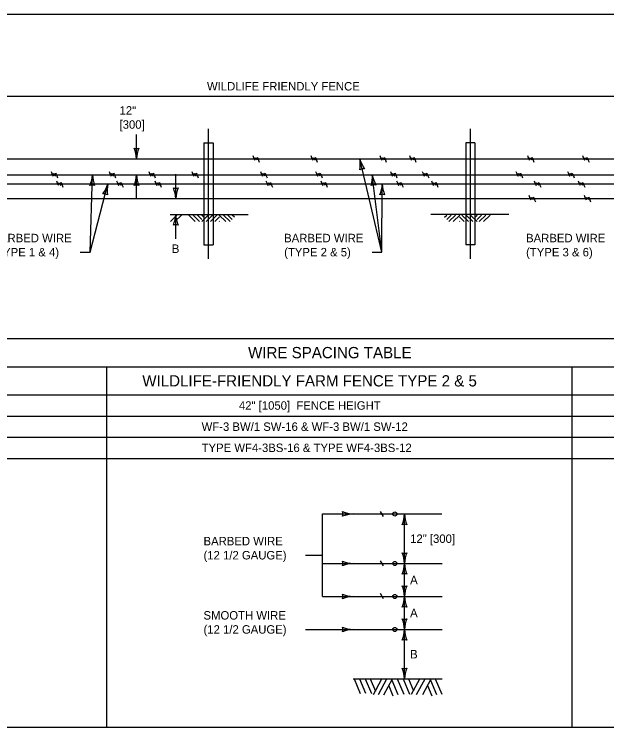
# Model space of a CAD drawing. Extents: x 49991.4 to 50021, y 49987.6 to 50011.4.
# Drawn here: x 50013.03 to 50017.23, y 50003.02 to 50008.16 of the extents above; entities that cross this region are included whole.
import ezdxf

# ---------------------------------------------------------------- set-up
doc = ezdxf.new("R2010")
doc.units = 0
for name, color, linetype in [('Level 1', 7, 'Continuous'), ('Level 2', 7, 'Continuous'), ('Level 3', 7, 'Continuous'), ('Level 4', 7, 'Continuous'), ('Level 5', 7, 'Continuous')]:
    doc.layers.add(name, color=color, linetype=linetype)

msp = doc.modelspace()

# ---------------------------------------------------------------- linework, layer by layer
at = {"layer": 'Level 1'}
for p, q in [((50014.3766, 50007.2536), (50014.3766, 50006.7473)), ((50014.3766, 50007.2536), (50014.4423, 50007.2536)), ((50014.4423, 50007.2536), (50014.4423, 50006.7473)), ((50016.2329, 50007.2536), (50016.2329, 50006.7473)), ((50016.2986, 50007.2536), (50016.2329, 50007.2536)), ((50016.2986, 50007.2536), (50016.2986, 50006.7473)), ((50012.5204, 50007.1411), (50018.1548, 50007.1411)), ((50012.5204, 50007.0286), (50018.1548, 50007.0286)), ((50012.5204, 50006.963), (50018.1548, 50006.963)), ((50010.2459, 50006.8598), (50020.4293, 50006.8598)), ((50014.1372, 50006.7473), (50014.6898, 50006.7473)), ((50014.1398, 50006.6964), (50014.186, 50006.7427)), ((50014.1706, 50006.6964), (50014.2169, 50006.7427)), ((50014.3153, 50006.6964), (50014.2691, 50006.7427)), ((50014.3462, 50006.6964), (50014.2999, 50006.7427)), ((50014.3616, 50006.7118), (50014.3307, 50006.7427)), ((50014.377, 50006.7273), (50014.3616, 50006.7427)), ((50014.3616, 50006.6964), (50014.4078, 50006.7427)), ((50014.3924, 50006.6964), (50014.4387, 50006.7427)), ((50014.4232, 50006.6964), (50014.4695, 50006.7427)), ((50014.4232, 50006.6964), (50014.4695, 50006.7427)), ((50014.4541, 50006.6964), (50014.487, 50006.7303)), ((50014.4541, 50006.6964), (50014.487, 50006.7303)), ((50014.5312, 50006.6964), (50014.4849, 50006.7427)), ((50014.562, 50006.6964), (50014.5158, 50006.7427)), ((50014.5774, 50006.7118), (50014.5466, 50006.7427)), ((50014.5929, 50006.7273), (50014.5774, 50006.7427)), ((50016.538, 50006.7473), (50015.9854, 50006.7473)), ((50016.0823, 50006.7273), (50016.0978, 50006.7427)), ((50016.0978, 50006.7118), (50016.1286, 50006.7427)), ((50016.1132, 50006.6964), (50016.1594, 50006.7427)), ((50016.144, 50006.6964), (50016.1903, 50006.7427)), ((50016.2211, 50006.6964), (50016.1882, 50006.7303)), ((50016.2211, 50006.6964), (50016.1882, 50006.7303)), ((50016.252, 50006.6964), (50016.2057, 50006.7427)), ((50016.252, 50006.6964), (50016.2057, 50006.7427)), ((50016.2828, 50006.6964), (50016.2365, 50006.7427)), ((50016.2828, 50006.6964), (50016.2365, 50006.7427)), ((50016.3136, 50006.6964), (50016.2674, 50006.7427)), ((50016.3136, 50006.6964), (50016.2674, 50006.7427)), ((50016.2982, 50006.7273), (50016.3136, 50006.7427)), ((50016.3136, 50006.7118), (50016.3445, 50006.7427)), ((50016.329, 50006.6964), (50016.3753, 50006.7427)), ((50016.3599, 50006.6964), (50016.4061, 50006.7427)), ((50014.4849, 50006.6964), (50014.487, 50006.6995)), ((50016.1903, 50006.6964), (50016.1882, 50006.6995)), ((50015.4352, 50004.6229), (50016.0639, 50004.6229)), ((50015.6508, 50004.6038), (50015.6288, 50004.64)), ((50015.6508, 50004.2556), (50015.6288, 50004.2917)), ((50015.4352, 50004.272), (50016.0659, 50004.272)), ((50015.4352, 50004.038), (50016.0659, 50004.038)), ((50015.6508, 50004.0216), (50015.6287, 50004.0578)), ((50015.4352, 50003.804), (50016.0659, 50003.804)), ((50015.4352, 50003.4531), (50016.0659, 50003.4531)), ((50015.4411, 50003.4531), (50015.4849, 50003.3492)), ((50015.4808, 50003.4531), (50015.5235, 50003.3518)), ((50015.5211, 50003.4531), (50015.5648, 50003.3492)), ((50015.556, 50003.4531), (50015.5922, 50003.3671)), ((50015.5797, 50003.3438), (50015.6385, 50003.4531)), ((50015.6141, 50003.3421), (50015.6738, 50003.4531)), ((50015.6527, 50003.3404), (50015.7133, 50003.4531)), ((50015.7082, 50003.4435), (50015.7505, 50003.3432)), ((50015.7479, 50003.4531), (50015.7935, 50003.3449)), ((50015.7887, 50003.4531), (50015.8339, 50003.3457)), ((50015.8269, 50003.4531), (50015.8624, 50003.3686)), ((50015.8495, 50003.3446), (50015.908, 50003.4531)), ((50015.8846, 50003.3421), (50015.9445, 50003.4531)), ((50015.9286, 50003.3421), (50015.9883, 50003.4531)), ((50015.9837, 50003.4444), (50016.0263, 50003.3432)), ((50016.0173, 50003.4531), (50016.0633, 50003.344)), ((50015.6867, 50003.4034), (50015.7159, 50003.3341)), ((50015.9627, 50003.4057), (50015.9936, 50003.3324))]:
    msp.add_line(p, q, dxfattribs=at)
msp.add_lwpolyline([(50020.9378, 50008.1646), (50009.7374, 50008.1646), (50009.7374, 49999.8856), (50020.9378, 49999.8856)], close=True, dxfattribs=at)
msp.add_lwpolyline([(50020.9378, 50008.1646), (50009.7374, 50008.1646), (50009.7374, 49999.8856), (50020.9378, 49999.8856)], close=True, dxfattribs=at)
for centre in [(50015.7304, 50004.6228), (50015.7304, 50004.2718), (50015.7303, 50004.0379), (50015.7303, 50003.8039)]:
    msp.add_circle(centre, 0.0146, dxfattribs=at)
for points in [[(50014.7232, 50007.1642), (50014.7386, 50007.1334), (50014.7386, 50007.1488), (50014.754, 50007.1334), (50014.754, 50007.1488), (50014.7694, 50007.118)], [(50015.1341, 50007.1642), (50015.1495, 50007.1334), (50015.1495, 50007.1488), (50015.1649, 50007.1334), (50015.1649, 50007.1488), (50015.1803, 50007.118)], [(50015.6236, 50007.1642), (50015.639, 50007.1334), (50015.639, 50007.1488), (50015.6544, 50007.1334), (50015.6544, 50007.1488), (50015.6699, 50007.118)], [(50015.8339, 50007.1642), (50015.8493, 50007.1334), (50015.8493, 50007.1488), (50015.8647, 50007.1334), (50015.8647, 50007.1488), (50015.8801, 50007.118)], [(50016.6704, 50007.1642), (50016.6858, 50007.1334), (50016.6858, 50007.1488), (50016.7012, 50007.1334), (50016.7012, 50007.1488), (50016.7166, 50007.118)], [(50017.0608, 50007.1642), (50017.0762, 50007.1334), (50017.0762, 50007.1488), (50017.0916, 50007.1334), (50017.0916, 50007.1488), (50017.107, 50007.118)], [(50013.2932, 50007.0517), (50013.3086, 50007.0209), (50013.3086, 50007.0363), (50013.3241, 50007.0209), (50013.3241, 50007.0363), (50013.3395, 50007.0055)], [(50013.704, 50007.0517), (50013.7194, 50007.0209), (50013.7194, 50007.0363), (50013.7348, 50007.0209), (50013.7348, 50007.0363), (50013.7502, 50007.0055)], [(50013.9853, 50007.0517), (50014.0007, 50007.0209), (50014.0007, 50007.0363), (50014.0161, 50007.0209), (50014.0161, 50007.0363), (50014.0315, 50007.0055)], [(50014.2901, 50007.0517), (50014.3055, 50007.0209), (50014.3055, 50007.0363), (50014.3209, 50007.0209), (50014.3209, 50007.0363), (50014.3363, 50007.0055)], [(50014.7779, 50007.0517), (50014.7933, 50007.0209), (50014.7933, 50007.0363), (50014.8087, 50007.0209), (50014.8087, 50007.0363), (50014.8241, 50007.0055)], [(50015.1689, 50007.0517), (50015.1843, 50007.0209), (50015.1843, 50007.0363), (50015.1997, 50007.0209), (50015.1997, 50007.0363), (50015.2151, 50007.0055)], [(50015.6989, 50007.0517), (50015.7143, 50007.0209), (50015.7143, 50007.0363), (50015.7297, 50007.0209), (50015.7297, 50007.0363), (50015.7451, 50007.0055)], [(50015.9248, 50007.0517), (50015.9402, 50007.0209), (50015.9402, 50007.0363), (50015.9556, 50007.0209), (50015.9556, 50007.0363), (50015.971, 50007.0055)], [(50016.5891, 50007.0517), (50016.6046, 50007.0209), (50016.6046, 50007.0363), (50016.62, 50007.0209), (50016.62, 50007.0363), (50016.6354, 50007.0055)], [(50016.9552, 50007.0517), (50016.9707, 50007.0209), (50016.9707, 50007.0363), (50016.9861, 50007.0209), (50016.9861, 50007.0363), (50017.0015, 50007.0055)], [(50013.3311, 50006.9861), (50013.3465, 50006.9553), (50013.3465, 50006.9707), (50013.362, 50006.9553), (50013.362, 50006.9707), (50013.3774, 50006.9398)], [(50013.7575, 50006.9861), (50013.7729, 50006.9553), (50013.7729, 50006.9707), (50013.7883, 50006.9553), (50013.7883, 50006.9707), (50013.8037, 50006.9398)], [(50014.0281, 50006.9861), (50014.0435, 50006.9553), (50014.0435, 50006.9707), (50014.0589, 50006.9553), (50014.0589, 50006.9707), (50014.0744, 50006.9398)], [(50014.816, 50006.9861), (50014.8314, 50006.9553), (50014.8314, 50006.9707), (50014.8468, 50006.9553), (50014.8468, 50006.9707), (50014.8622, 50006.9398)], [(50015.2055, 50006.9861), (50015.2209, 50006.9553), (50015.2209, 50006.9707), (50015.2363, 50006.9553), (50015.2363, 50006.9707), (50015.2517, 50006.9398)], [(50015.7424, 50006.9861), (50015.7578, 50006.9553), (50015.7578, 50006.9707), (50015.7732, 50006.9553), (50015.7732, 50006.9707), (50015.7886, 50006.9398)], [(50015.9899, 50006.9861), (50016.0054, 50006.9553), (50016.0054, 50006.9707), (50016.0208, 50006.9553), (50016.0208, 50006.9707), (50016.0362, 50006.9398)], [(50016.718, 50006.9861), (50016.7334, 50006.9553), (50016.7334, 50006.9707), (50016.7488, 50006.9553), (50016.7488, 50006.9707), (50016.7643, 50006.9398)], [(50017.0299, 50006.9861), (50017.0453, 50006.9553), (50017.0453, 50006.9707), (50017.0608, 50006.9553), (50017.0608, 50006.9707), (50017.0762, 50006.9398)], [(50016.6801, 50006.8829), (50016.6955, 50006.8521), (50016.6955, 50006.8675), (50016.7109, 50006.8521), (50016.7109, 50006.8675), (50016.7264, 50006.8367)], [(50017.0721, 50006.8829), (50017.0875, 50006.8521), (50017.0875, 50006.8675), (50017.1029, 50006.8521), (50017.1029, 50006.8675), (50017.1183, 50006.8367)]]:
    msp.add_spline(points, degree=3, dxfattribs=at)
at = {"layer": 'Level 2'}
for p, q in [((50010.3885, 50005.867), (50020.2867, 50005.867)), ((50010.3885, 50005.667), (50020.2867, 50005.667)), ((50013.6879, 50003.11), (50013.6879, 50005.667)), ((50016.9873, 50003.11), (50016.9873, 50005.667)), ((50016.9873, 50005.667), (50017.1543, 50005.667)), ((50010.3885, 50005.467), (50020.2867, 50005.467)), ((50010.3885, 50005.317), (50020.2867, 50005.317)), ((50010.3885, 50005.167), (50020.2867, 50005.167)), ((50010.3885, 50005.017), (50020.2867, 50005.017)), ((50010.3885, 50003.11), (50020.2867, 50003.11))]:
    msp.add_line(p, q, dxfattribs=at)
at = {"layer": 'Level 3'}
for p, q in [((50012.5532, 50007.5857), (50018.122, 50007.5857)), ((50013.899, 50007.1411), (50013.899, 50007.3145)), ((50015.6386, 50006.4793), (50015.4817, 50007.1411)), ((50013.5705, 50006.4793), (50013.5876, 50007.0286)), ((50013.899, 50006.8552), (50013.899, 50007.0286)), ((50014.1772, 50006.8598), (50014.1772, 50007.0332)), ((50015.6386, 50006.4793), (50015.5706, 50007.0286)), ((50013.5705, 50006.4793), (50013.6956, 50006.963)), ((50015.6386, 50006.4793), (50015.6414, 50006.963)), ((50014.1772, 50006.5739), (50014.1772, 50006.7473)), ((50013.5005, 50006.4793), (50013.5705, 50006.4793)), ((50015.5686, 50006.4793), (50015.6386, 50006.4793)), ((50015.217, 50004.6229), (50015.4304, 50004.6229)), ((50015.217, 50004.6229), (50015.4352, 50004.6229)), ((50015.2181, 50004.0379), (50015.217, 50004.6229)), ((50015.7987, 50004.272), (50015.7987, 50004.6229)), ((50015.7987, 50004.272), (50015.7987, 50004.6229)), ((50015.0965, 50004.3304), (50015.2175, 50004.3304)), ((50015.217, 50004.272), (50015.4352, 50004.272)), ((50015.7987, 50004.038), (50015.7987, 50004.272)), ((50015.2181, 50004.0379), (50015.4352, 50004.038)), ((50015.7986, 50003.8039), (50015.7986, 50004.038)), ((50015.0965, 50003.804), (50015.4352, 50003.804)), ((50015.217, 50003.804), (50015.4304, 50003.804)), ((50015.7986, 50003.4531), (50015.7986, 50003.804))]:
    msp.add_line(p, q, dxfattribs=at)
for centre, radius, start, end in [((50013.6768, 50007.1319), 0.2223, 2.3605, 22.544), ((50013.899, 50007.2693), 0.0548, 252.1388, 287.8612), ((50014.1317, 50007.1296), 0.233, 157.9228, 177.1727), ((50015.6958, 50007.2012), 0.2223, 195.6916, 215.8751), ((50015.2526, 50007.0986), 0.233, 351.2539, 10.5038), ((50015.5113, 50007.0163), 0.0548, 85.4699, 121.1923), ((50013.3553, 50007.0473), 0.233, 336.1385, 355.3883), ((50013.8099, 50007.0308), 0.2223, 180.5761, 200.7596), ((50013.6662, 50007.0401), 0.233, 337.9228, 357.1727), ((50014.1211, 50007.0377), 0.2223, 182.3605, 202.544), ((50015.3382, 50007.0114), 0.233, 344.9777, 4.2275), ((50015.7899, 50007.065), 0.2223, 189.4153, 209.5988), ((50013.4731, 50007.0324), 0.233, 323.4203, 342.6701), ((50013.9129, 50006.9162), 0.2223, 167.8579, 188.0414), ((50015.4088, 50006.9758), 0.233, 337.5844, 356.8342), ((50015.8636, 50006.9708), 0.2223, 182.022, 202.2055), ((50013.5836, 50006.9004), 0.0548, 70.3544, 106.0768), ((50013.899, 50006.9004), 0.0548, 72.1388, 107.8612), ((50013.955, 50006.8506), 0.2223, 2.3605, 22.544), ((50014.1772, 50006.988), 0.0548, 252.1388, 287.8612), ((50014.4099, 50006.8483), 0.233, 157.9228, 177.1727), ((50015.5863, 50006.9013), 0.0548, 79.1936, 114.916), ((50013.6635, 50006.8388), 0.0548, 57.6362, 93.3586), ((50015.6407, 50006.8348), 0.0548, 71.8003, 107.5227), ((50013.9445, 50006.7588), 0.233, 337.9228, 357.1727), ((50014.3993, 50006.7565), 0.2223, 182.3605, 202.544), ((50014.1772, 50006.6191), 0.0548, 72.1388, 107.8612), ((50015.4444, 50004.8451), 0.2223, 247.456, 267.6395), ((50015.307, 50004.6229), 0.0548, 342.1388, 17.8612), ((50015.4467, 50004.3902), 0.233, 92.8273, 112.0772), ((50015.5659, 50004.6344), 0.233, 337.9228, 357.1727), ((50016.0208, 50004.6321), 0.2223, 182.3605, 202.544), ((50015.7987, 50004.4947), 0.0548, 72.1388, 107.8612), ((50015.5765, 50004.2628), 0.2223, 2.3605, 22.544), ((50015.7987, 50004.4002), 0.0548, 252.1388, 287.8612), ((50016.0314, 50004.2605), 0.233, 157.9228, 177.1727), ((50015.4444, 50004.4941), 0.2223, 247.456, 267.6395), ((50015.307, 50004.272), 0.0548, 342.1388, 17.8612), ((50015.4467, 50004.0393), 0.233, 92.8273, 112.0772), ((50015.5659, 50004.2835), 0.233, 337.9228, 357.1727), ((50016.0208, 50004.2811), 0.2223, 182.3605, 202.544), ((50015.7987, 50004.1438), 0.0548, 72.1388, 107.8612), ((50015.5765, 50004.0289), 0.2223, 2.3605, 22.544), ((50015.7987, 50004.1662), 0.0548, 252.1388, 287.8612), ((50016.0314, 50004.0265), 0.233, 157.9228, 177.1727), ((50015.4444, 50004.2601), 0.2223, 247.456, 267.6395), ((50015.307, 50004.038), 0.0548, 342.1388, 17.8612), ((50015.4467, 50003.8053), 0.233, 92.8273, 112.0772), ((50015.5659, 50004.0495), 0.233, 337.9228, 357.1727), ((50016.0207, 50004.0472), 0.2223, 182.3605, 202.544), ((50015.7986, 50003.9098), 0.0548, 72.1388, 107.8612), ((50015.5765, 50003.7948), 0.2223, 2.3605, 22.544), ((50015.7986, 50003.9321), 0.0548, 252.1388, 287.8612), ((50016.0313, 50003.7924), 0.233, 157.9228, 177.1727), ((50015.4444, 50004.0262), 0.2223, 247.456, 267.6395), ((50015.307, 50003.804), 0.0548, 342.1388, 17.8612), ((50015.4467, 50003.5713), 0.233, 92.8273, 112.0772), ((50015.5659, 50003.8155), 0.233, 337.9228, 357.1727), ((50016.0207, 50003.8132), 0.2223, 182.3605, 202.544), ((50015.7986, 50003.6758), 0.0548, 72.1388, 107.8612), ((50015.5765, 50003.4439), 0.2223, 2.3605, 22.544), ((50015.7986, 50003.5813), 0.0548, 252.1388, 287.8612), ((50016.0313, 50003.4416), 0.233, 157.9228, 177.1727)]:
    msp.add_arc(centre, radius, start, end, dxfattribs=at)
at = {"layer": 'Level 4'}
for p, q in [((50014.3766, 50006.7473), (50014.3766, 50006.5317)), ((50014.4423, 50006.7473), (50014.4423, 50006.5317)), ((50016.2329, 50006.7473), (50016.2329, 50006.5317)), ((50016.2986, 50006.7473), (50016.2986, 50006.5317)), ((50014.3766, 50006.5317), (50014.4423, 50006.5317)), ((50016.2986, 50006.5317), (50016.2329, 50006.5317))]:
    msp.add_line(p, q, dxfattribs=at)
at = {"layer": 'Level 5'}
for p, q in [((50014.4095, 50006.4316), (50014.4095, 50007.3536)), ((50016.2657, 50006.4316), (50016.2657, 50007.3536))]:
    msp.add_line(p, q, dxfattribs=at)

# ---------------------------------------------------------------- texts
at = {"layer": 'Level 2'}
for s, height, p in [('WILDLIFE FRIENDLY FENCE', 0.06, (50014.3986, 50007.6257)), ('12"', 0.06, (50013.7787, 50007.4545)), ('[300]', 0.06, (50013.7787, 50007.3545)), ('BARBED WIRE', 0.06, (50012.8775, 50006.5493)), ('BARBED WIRE', 0.06, (50014.9456, 50006.5493)), ('BARBED WIRE', 0.06, (50016.6607, 50006.5493)), ('(TYPE 1 & 4)', 0.06, (50012.8775, 50006.4493)), ('B', 0.06, (50014.1494, 50006.4739)), ('(TYPE 2 & 5)', 0.06, (50014.9456, 50006.4493)), ('(TYPE 3 & 6)', 0.06, (50016.6607, 50006.4493)), ('WIRE SPACING TABLE', 0.08, (50014.6899, 50005.727)), ('WILDLIFE-FRIENDLY FARM FENCE TYPE 2 & 5', 0.08, (50013.9401, 50005.527)), ('42" [1050]  FENCE HEIGHT', 0.06, (50014.6249, 50005.362)), ('WF-3 BW/1 SW-16 & WF-3 BW/1 SW-12', 0.06, (50014.3606, 50005.212)), ('TYPE WF4-3BS-16 & TYPE WF4-3BS-12', 0.06, (50014.3606, 50005.062)), ('BARBED WIRE', 0.06, (50014.3741, 50004.4004)), ('12" [300]', 0.06, (50015.8387, 50004.4175)), ('(12 1/2 GAUGE)', 0.06, (50014.3741, 50004.3004)), ('A', 0.06, (50015.8387, 50004.125)), ('SMOOTH WIRE', 0.06, (50014.374, 50003.874)), ('A', 0.06, (50015.8386, 50003.8909)), ('(12 1/2 GAUGE)', 0.06, (50014.374, 50003.774)), ('B', 0.06, (50015.8386, 50003.5985))]:
    msp.add_text(s, height=height, dxfattribs=at).set_placement(p)

doc.saveas('drawing.dxf')
